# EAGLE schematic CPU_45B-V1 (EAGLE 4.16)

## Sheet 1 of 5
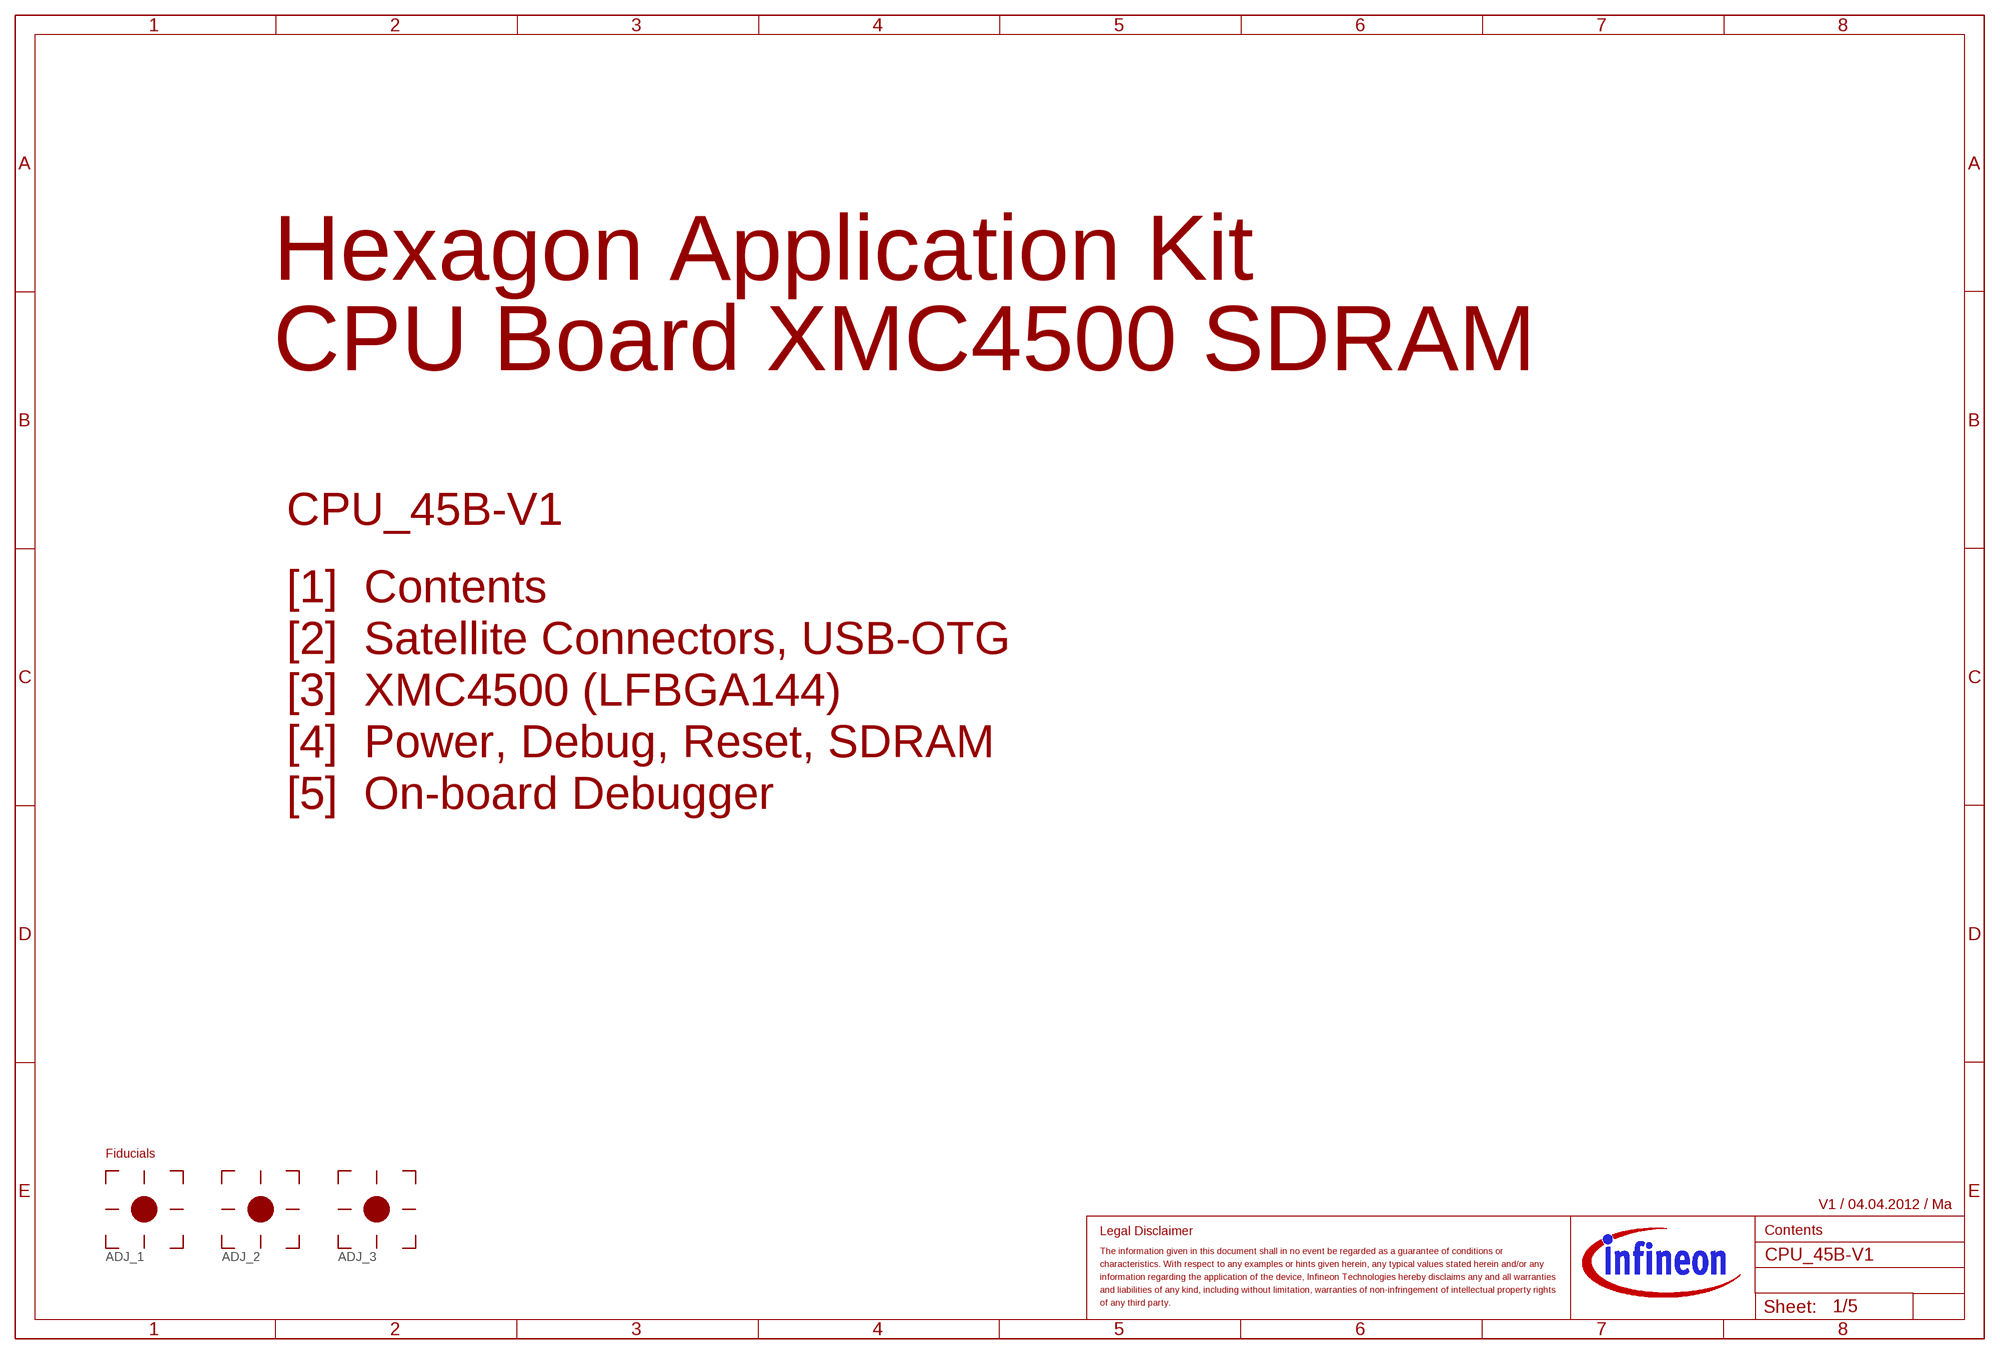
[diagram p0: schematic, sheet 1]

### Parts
ADJ_1  FIDUCIAL  [FIDUCIAL]
ADJ_2  FIDUCIAL  [FIDUCIAL]
ADJ_3  FIDUCIAL  [FIDUCIAL]

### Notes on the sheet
- Hexagon Application Kit
- CPU Board XMC4500 SDRAM
- CPU_45B-V1
- [1]  Contents
- [2]  Satellite Connectors, USB-OTG
- [3]  XMC4500 (LFBGA144)
- [4]  Power, Debug, Reset, SDRAM
- [5]  On-board Debugger
- Fiducials
- V1 / 04.04.2012 / Ma
- Contents

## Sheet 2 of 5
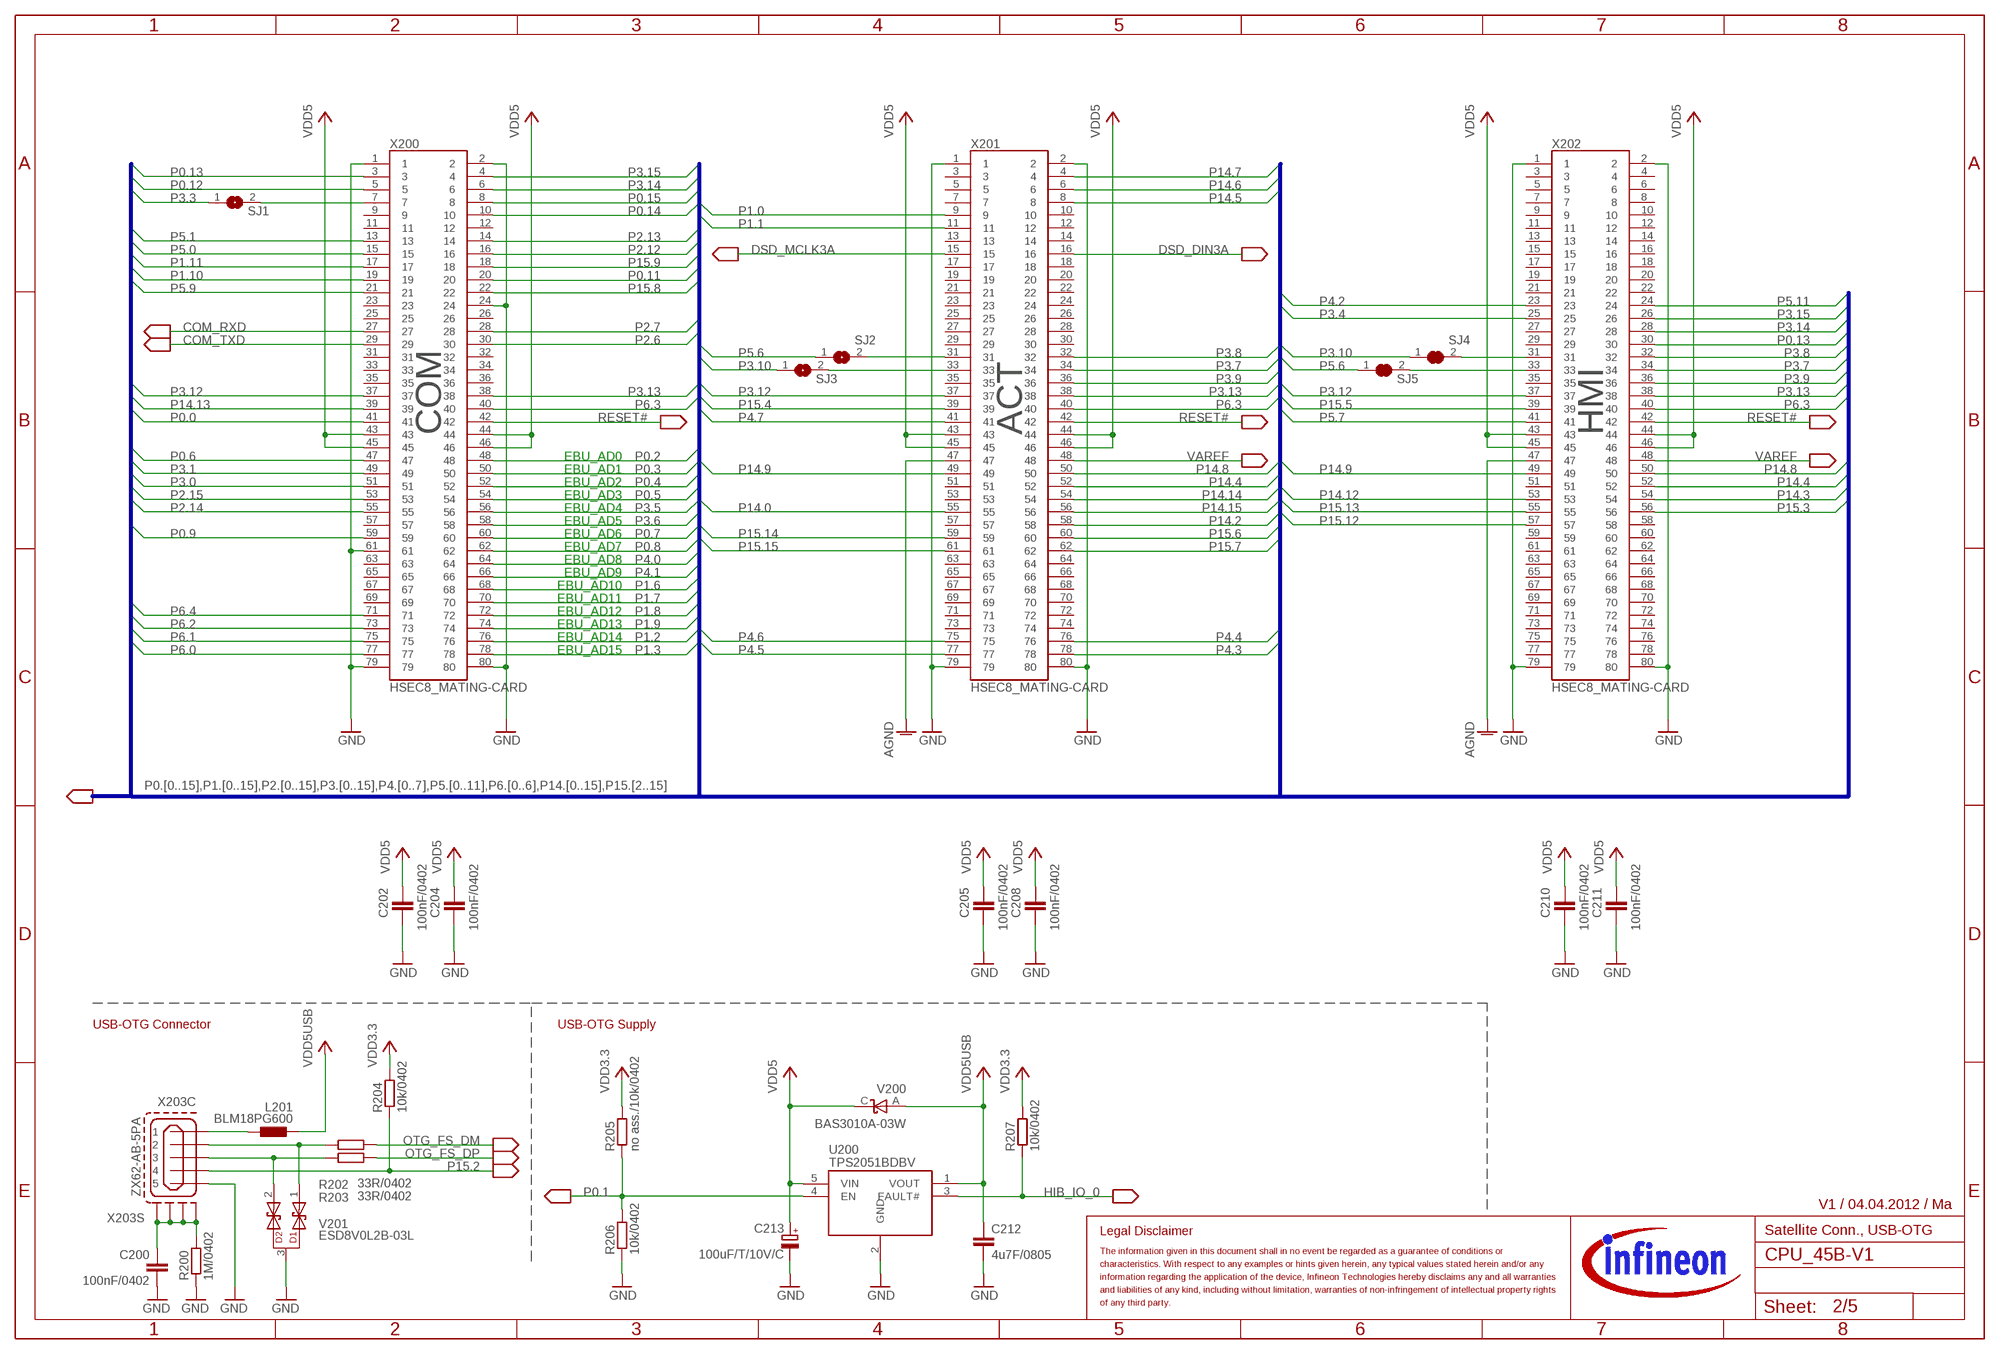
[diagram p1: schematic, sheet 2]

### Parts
C200  100nF/0402  C-EUC06030402  [C0402]
C202  100nF/0402  C-EUC06030402  [C0402]
C204  100nF/0402  C-EUC06030402  [C0402]
C205  100nF/0402  C-EUC06030402  [C0402]
C208  100nF/0402  C-EUC06030402  [C0402]
C210  100nF/0402  C-EUC06030402  [C0402]
C211  100nF/0402  C-EUC06030402  [C0402]
C212  4u7F/0805  C-EUC0805K  [C0805K]
C213  100uF/T/10V/C  CPOL-EUSMCC  [SMC_C]
L201  BLM18PG600  L_EU_L0603  [L1608]
R200  1M/0402  R-EU_R06030402  [R0402]
R202  33R/0402  R-EU_R06030402  [R0402]
R203  33R/0402  R-EU_R06030402  [R0402]
R204  10k/0402  R-EU_R06030402  [R0402]
R205  no ass./10k/0402  R-EU_R06030402  [R0402]
R206  10k/0402  R-EU_R06030402  [R0402]
R207  10k/0402  R-EU_R06030402  [R0402]
SJ1  SJ0402PASTE  [R0402]
SJ2  SJ0402PASTE  [R0402]
SJ3  SJ0402PASTE  [R0402]
SJ4  SJ0402PASTE  [R0402]
SJ5  SJ0402PASTE  [R0402]
U200  TPS2051BDBV  STMPS2151STR  [SOT23-5L]
V200  BAS3010A-03W  BAT60  [SOD323-R]
V201  ESD8V0L2B-03L  [TSLP-3-1]
X200  HSEC8_MATING-CARD  [HSEC8_MATING-CARD_80]
X201  HSEC8_MATING-CARD  [HSEC8_MATING-CARD_80]
X202  HSEC8_MATING-CARD  [HSEC8_MATING-CARD_80]
X203  ZX62-AB-5PA  ZX62-AB-5PA_MICRO-USB  [ZX62-AB-5PA_MICRO-USB]

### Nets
AGND: X201.47 X202.47 ; also sheet 3
COM_RXD: X200.27 ; also sheet 3
COM_TXD: X200.29 ; also sheet 3
DSD_DIN3A: X201.16 ; also sheet 3
DSD_MCLK3A: X201.15 ; also sheet 3
GND: C200.2 C202.2 C204.2 C205.2 C208.2 C210.2 C211.2 C212.2 C213.- R200.1 R206.1 U200.2(GND) V201.3 X200.1 X200.2 X200.24 X200.61 X200.79 X200.80 X201.1 X201.2 X201.79 X201.80 X202.1 X202.2 X202.79 X202.80 X203.5 ; also sheet 3,4,5
HIB_IO_0: R207.1 U200.3(FAULT#) ; also sheet 3
N$4: L201.1 X203.1
N$5: R203.1 V201.2 X203.3
N$6: R202.1 V201.1 X203.2
N$28: C200.1 R200.2 X203.S1(S:S1) X203.S2(S:S2) X203.S3(S:S3) X203.S4(S:S4)
N$32: SJ3.2 X201.33
N$48: SJ5.2 X202.33
N$49: SJ1.2 X200.7
N$52: SJ4.2 X202.31
N$53: SJ2.2 X201.31
OTG_FS_DM: R202.2 ; also sheet 3
OTG_FS_DP: R203.2 ; also sheet 3
P0.0: X200.41 ; also sheet 3
P0.1: R205.1 R206.2 U200.4(EN) ; also sheet 3
P0.2: X200.48 ; also sheet 3,4
P0.3: X200.50 ; also sheet 3,4
P0.4: X200.52 ; also sheet 3,4
P0.5: X200.54 ; also sheet 3,4
P0.6: X200.47 ; also sheet 3
P0.7: X200.60 ; also sheet 3,4,5
P0.8: X200.62 ; also sheet 3,4
P0.9: X200.59 ; also sheet 3
P0.11: X200.20 ; also sheet 3
P0.12: X200.5 ; also sheet 3
P0.13: X200.3 X202.30 ; also sheet 3
P0.14: X200.10 ; also sheet 3
P0.15: X200.8 ; also sheet 3
P1.0: X201.9 ; also sheet 3
P1.1: X201.11 ; also sheet 3
P1.2: X200.76 ; also sheet 3,4
P1.3: X200.78 ; also sheet 3,4
P1.6: X200.68 ; also sheet 3,4
P1.7: X200.70 ; also sheet 3,4
P1.8: X200.72 ; also sheet 3,4
P1.9: X200.74 ; also sheet 3,4
P1.10: X200.19 ; also sheet 3
P1.11: X200.17 ; also sheet 3
P2.6: X200.30 ; also sheet 3
P2.7: X200.28 ; also sheet 3
P2.12: X200.16 ; also sheet 3
P2.13: X200.14 ; also sheet 3
P2.14: X200.55 ; also sheet 3,4
P2.15: X200.53 ; also sheet 3,4
P3.0: X200.51 ; also sheet 3
P3.1: X200.49 ; also sheet 3,4
P3.3: SJ1.1 ; also sheet 3
P3.4: X202.25 ; also sheet 3
P3.5: X200.56 ; also sheet 3,4
P3.6: X200.58 ; also sheet 3,4
P3.7: X201.34 X202.34 ; also sheet 3
P3.8: X201.32 X202.32 ; also sheet 3
P3.9: X201.36 X202.36 ; also sheet 3
P3.10: SJ3.1 SJ4.1 ; also sheet 3
P3.12: X200.37 X201.37 X202.37 ; also sheet 3
P3.13: X200.38 X201.38 X202.38 ; also sheet 3
P3.14: X200.6 X202.28 ; also sheet 3
P3.15: X200.4 X202.26 ; also sheet 3
P4.0: X200.64 ; also sheet 3,4
P4.1: X200.66 ; also sheet 3,4
P4.2: X202.23 ; also sheet 3
P4.3: X201.78 ; also sheet 3
P4.4: X201.76 ; also sheet 3
P4.5: X201.77 ; also sheet 3
P4.6: X201.75 ; also sheet 3
P4.7: X201.41 ; also sheet 3
P5.0: X200.15 ; also sheet 3
P5.1: X200.13 ; also sheet 3
P5.6: SJ2.1 SJ5.1 ; also sheet 3
P5.7: X202.41 ; also sheet 3
P5.9: X200.21 ; also sheet 3
P5.11: X202.24 ; also sheet 3
P6.0: X200.77 ; also sheet 3,4
P6.1: X200.75 ; also sheet 3,4
P6.2: X200.73 ; also sheet 3,4
P6.3: X200.40 X201.40 X202.40 ; also sheet 3
P6.4: X200.71 ; also sheet 3,4
P14.0: X201.55 ; also sheet 3
P14.2: X201.58 ; also sheet 3
P14.3: X202.54 ; also sheet 3
P14.4: X201.52 X202.52 ; also sheet 3
P14.5: X201.8 ; also sheet 3
P14.6: X201.6 ; also sheet 3
P14.7: X201.4 ; also sheet 3
P14.8: X201.50 X202.50 ; also sheet 3
P14.9: X201.49 X202.49 ; also sheet 3
P14.12: X202.53 ; also sheet 3
P14.13: X200.39 ; also sheet 3
P14.14: X201.54 ; also sheet 3
P14.15: X201.56 ; also sheet 3
P15.2: R204.1 X203.4 ; also sheet 3
P15.3: X202.56 ; also sheet 3
P15.4: X201.39 ; also sheet 3
P15.5: X202.39 ; also sheet 3
P15.6: X201.60 ; also sheet 3
P15.7: X201.62 ; also sheet 3
P15.8: X200.22 ; also sheet 3
P15.9: X200.18 ; also sheet 3
P15.12: X202.57 ; also sheet 3
P15.13: X202.55 ; also sheet 3
P15.14: X201.59 ; also sheet 3
P15.15: X201.61 ; also sheet 3
RESET#: X200.42 X201.42 X202.42 ; also sheet 3,4,5
VAREF: X201.48 X202.48 ; also sheet 3
VDD3.3: R204.2 R205.2 R207.2 ; also sheet 3,4,5
VDD5: C202.1 C204.1 C205.1 C208.1 C210.1 C211.1 C213.+ U200.5(VIN) V200.C X200.43 X200.44 X200.45 X200.46 X201.43 X201.44 X201.45 X201.46 X202.43 X202.44 X202.45 X202.46 ; also sheet 4,5
VDD5USB: C212.1 L201.2 U200.1(VOUT) V200.A ; also sheet 3,4
Unconnected: X200.9 X200.11 X200.12 X200.23 X200.25 X200.26 X200.31 X200.32 X200.33 X200.34 X200.35 X200.36 X200.57 X200.63 X200.65 X200.67 X200.69 X201.3 X201.5 X201.7 X201.10 X201.12 X201.13 X201.14 X201.17 X201.18 X201.19 X201.20 X201.21 X201.22 X201.23 X201.24 X201.25 X201.26 X201.27 X201.28 X201.29 X201.30 X201.35 X201.51 X201.53 X201.57 X201.63 X201.64 X201.65 X201.66 X201.67 X201.68 X201.69 X201.70 X201.71 X201.72 X201.73 X201.74 X202.3 X202.4 X202.5 X202.6 X202.7 X202.8 X202.9 X202.10 X202.11 X202.12 X202.13 X202.14 X202.15 X202.16 X202.17 X202.18 X202.19 X202.20 X202.21 X202.22 X202.27 X202.29 X202.35 X202.51 X202.58 X202.59 X202.60 X202.61 X202.62 X202.63 X202.64 X202.65 X202.66 X202.67 X202.68 X202.69 X202.70 X202.71 X202.72 X202.73 X202.74 X202.75 X202.76 X202.77 X202.78

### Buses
P0.[0..15],P1.[0..15],P2.[0..15],P3.[0..15],P4.[0..7],P5.[0..11],P6.[0..6],P14.[0..15],P15.[2..15]

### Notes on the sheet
- COM | ACT | HMI
- EBU_AD0
- EBU_AD1
- EBU_AD2
- EBU_AD3
- EBU_AD4
- EBU_AD5
- EBU_AD6
- EBU_AD7
- EBU_AD8
- EBU_AD9
- EBU_AD10
- EBU_AD11
- EBU_AD12
- EBU_AD13
- EBU_AD14
- EBU_AD15
- USB-OTG Connector | USB-OTG Supply
- V1 / 04.04.2012 / Ma
- Satellite Conn., USB-OTG

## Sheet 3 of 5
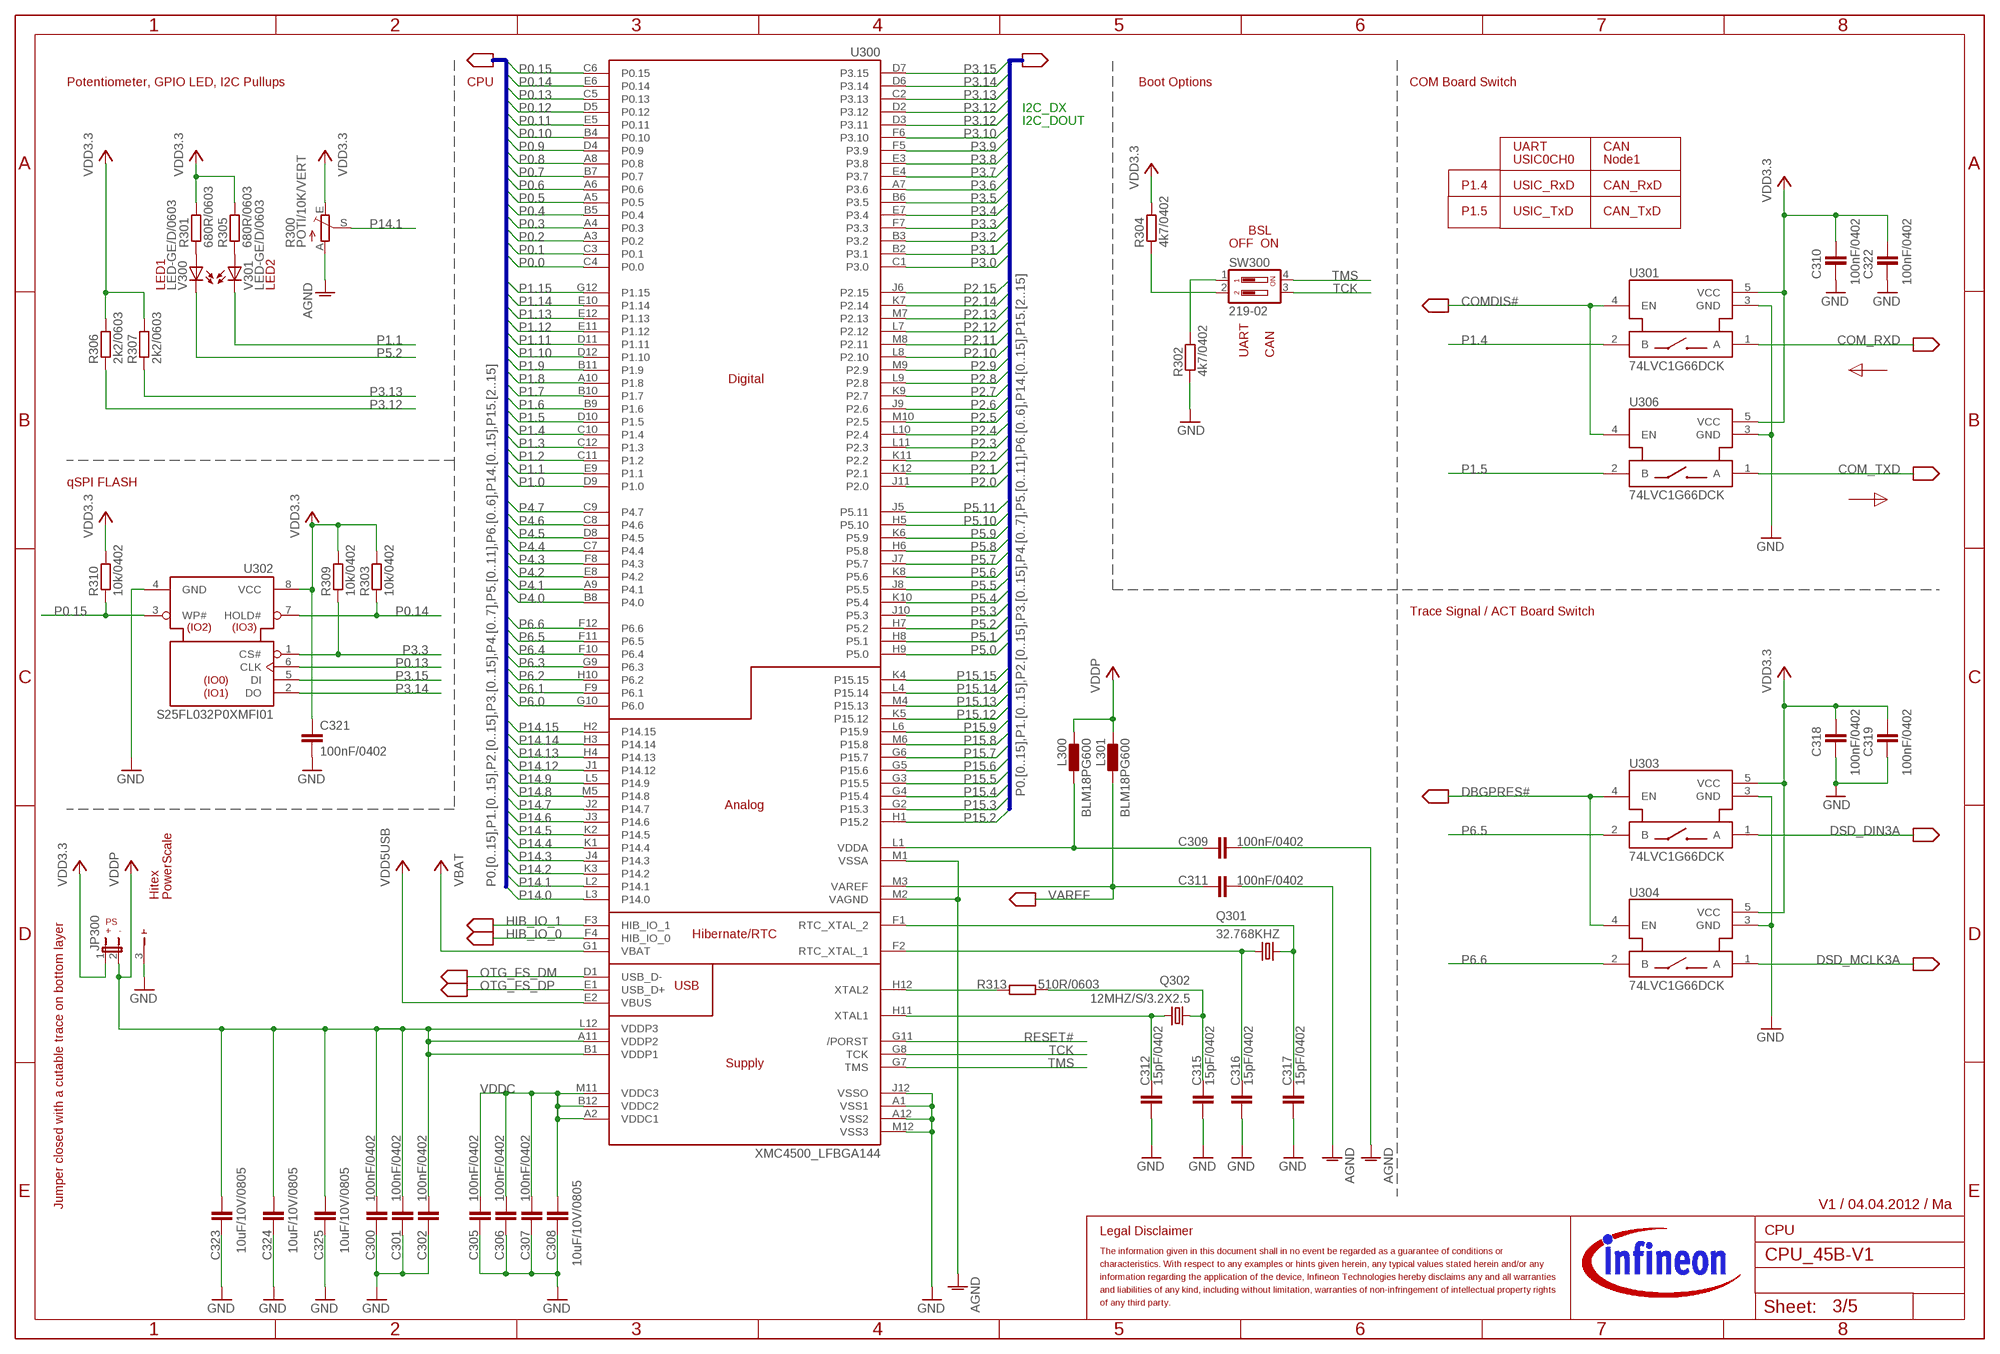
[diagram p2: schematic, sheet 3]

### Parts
C300  100nF/0402  C-EUC06030402  [C0402]
C301  100nF/0402  C-EUC06030402  [C0402]
C302  100nF/0402  C-EUC06030402  [C0402]
C305  100nF/0402  C-EUC06030402  [C0402]
C306  100nF/0402  C-EUC06030402  [C0402]
C307  100nF/0402  C-EUC06030402  [C0402]
C308  10uF/10V/0805  C-EUC0805K  [C0805K]
C309  100nF/0402  C-EUC06030402  [C0402]
C310  100nF/0402  C-EUC06030402  [C0402]
C311  100nF/0402  C-EUC06030402  [C0402]
C312  15pF/0402  C-EUC06030402  [C0402]
C315  15pF/0402  C-EUC06030402  [C0402]
C316  15pF/0402  C-EUC06030402  [C0402]
C317  15pF/0402  C-EUC06030402  [C0402]
C318  100nF/0402  C-EUC06030402  [C0402]
C319  100nF/0402  C-EUC06030402  [C0402]
C321  100nF/0402  C-EUC06030402  [C0402]
C322  100nF/0402  C-EUC06030402  [C0402]
C323  10uF/10V/0805  C-EUC0805K  [C0805K]
C324  10uF/10V/0805  C-EUC0805K  [C0805K]
C325  10uF/10V/0805  C-EUC0805K  [C0805K]
JP300  POWERSCALEMIR_SW  [PS3_MIRROR_SW]
L300  BLM18PG600  L_EU_L0603  [L1608]
L301  BLM18PG600  L_EU_L0603  [L1608]
Q301  32.768KHZ  FC135-32.768KHZ  [FC-135]
Q302  12MHZ/S/3.2X2.5  NX3225_22PAD  [32X25_2PAD]
R300  POTI/10K/VERT  [POTI]
R301  680R/0603  R-EU_R0603  [R0603]
R302  4k7/0402  R-EU_R06030402  [R0402]
R303  10k/0402  R-EU_R06030402  [R0402]
R304  4k7/0402  R-EU_R06030402  [R0402]
R305  680R/0603  R-EU_R0603  [R0603]
R306  2k2/0603  R-EU_R0603  [R0603]
R307  2k2/0603  R-EU_R0603  [R0603]
R309  10k/0402  R-EU_R06030402  [R0402]
R310  10k/0402  R-EU_R06030402  [R0402]
R313  510R/0603  R-EU_R0603  [R0603]
SW300  219-02  [CTS-219-02]
U300  XMC4500_LFBGA144  [P/PG-LFBGA-144-9]
U301  74LVC1G66DCK  74LVC1G66+PWRDCK  [SC70-5L]
U302  S25FL032P0XMFI01  W25Q80BVSSIG  [SO08W]
U303  74LVC1G66DCK  74LVC1G66+PWRDCK  [SC70-5L]
U304  74LVC1G66DCK  74LVC1G66+PWRDCK  [SC70-5L]
U306  74LVC1G66DCK  74LVC1G66+PWRDCK  [SC70-5L]
V300  LED-GE/D/0603  LEDCHIPLED_0603  [CHIPLED_0603]
V301  LED-GE/D/0603  LEDCHIPLED_0603  [CHIPLED_0603]

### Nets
AGND: C309.2 C311.2 R300.A U300.M1(VSSA) U300.M2(VAGND) ; also sheet 2
COM_RXD: U301.1(A) ; also sheet 2
COM_TXD: U306.1(A) ; also sheet 2
COMDIS#: U301.4(EN) U306.4(EN) ; also sheet 4,5
DBGPRES#: U303.4(EN) U304.4(EN) ; also sheet 4,5
DSD_DIN3A: U303.1(A) ; also sheet 2
DSD_MCLK3A: U304.1(A) ; also sheet 2
GND: C300.2 C301.2 C302.2 C305.2 C306.2 C307.2 C308.2 C310.2 C312.2 C315.2 C316.2 C317.2 C318.2 C319.2 C321.2 C322.2 C323.2 C324.2 C325.2 JP300.3(G) R302.1 U300.A1(VSS1) U300.A12(VSS2) U300.J12(VSSO) U300.M12(VSS3) U301.3(GND) U302.4(GND) U303.3(GND) U304.3(GND) U306.3(GND) ; also sheet 2,4,5
HIB_IO_0: U300.F4(HIB_IO_0) ; also sheet 2
HIB_IO_1: U300.F3(HIB_IO_1) ; also sheet 4
N$1: R304.1 SW300.2
N$2: R302.2 SW300.1
N$3: C309.1 L300.1 U300.L1(VDDA)
N$13: C312.1 Q302.2 U300.H11(XTAL1)
N$33: R305.1 V301.A
N$38: C316.1 Q301.P$1 U300.F2(RTC_XTAL_1)
N$39: R301.1 V300.A
N$40: C315.1 Q302.1 R313.2
N$42: C317.1 Q301.P$2 U300.F1(RTC_XTAL_2)
N$43: R313.1 U300.H12(XTAL2)
OTG_FS_DM: U300.D1(USB_D-) ; also sheet 2
OTG_FS_DP: U300.E1(USB_D+) ; also sheet 2
P0.0: U300.C4(P0.0) ; also sheet 2
P0.1: U300.C3(P0.1) ; also sheet 2
P0.2: U300.A3(P0.2) ; also sheet 2,4
P0.3: U300.A4(P0.3) ; also sheet 2,4
P0.4: U300.B5(P0.4) ; also sheet 2,4
P0.5: U300.A5(P0.5) ; also sheet 2,4
P0.6: U300.A6(P0.6) ; also sheet 2
P0.7: U300.B7(P0.7) ; also sheet 2,4,5
P0.8: U300.A8(P0.8) ; also sheet 2,4
P0.9: U300.D4(P0.9) ; also sheet 2
P0.10: U300.B4(P0.10) ; also sheet 4
P0.11: U300.E5(P0.11) ; also sheet 2
P0.12: U300.D5(P0.12) ; also sheet 2
P0.13: U300.C5(P0.13) U302.6(CLK) ; also sheet 2
P0.14: R303.1 U300.E6(P0.14) U302.7(HOLD#) ; also sheet 2
P0.15: R310.1 U300.C6(P0.15) U302.3(WP#) ; also sheet 2
P1.0: U300.D9(P1.0) ; also sheet 2
P1.1: U300.E9(P1.1) V301.C ; also sheet 2
P1.2: U300.C11(P1.2) ; also sheet 2,4
P1.3: U300.C12(P1.3) ; also sheet 2,4
P1.4: U300.C10(P1.4) U301.2(B) ; also sheet 4,5
P1.5: U300.D10(P1.5) U306.2(B) ; also sheet 4,5
P1.6: U300.B9(P1.6) ; also sheet 2,4
P1.7: U300.B10(P1.7) ; also sheet 2,4
P1.8: U300.A10(P1.8) ; also sheet 2,4
P1.9: U300.B11(P1.9) ; also sheet 2,4
P1.10: U300.D12(P1.10) ; also sheet 2
P1.11: U300.D11(P1.11) ; also sheet 2
P1.12: U300.E11(P1.12) ; also sheet 4
P1.13: U300.E12(P1.13) ; also sheet 4
P1.14: U300.E10(P1.14) ; also sheet 4
P1.15: U300.G12(P1.15) ; also sheet 4
P2.0: U300.J11(P2.0) ; also sheet 4
P2.1: U300.K12(P2.1) ; also sheet 4,5
P2.2: U300.K11(P2.2) ; also sheet 4
P2.3: U300.L11(P2.3) ; also sheet 4
P2.4: U300.L10(P2.4) ; also sheet 4
P2.5: U300.M10(P2.5) ; also sheet 4
P2.6: U300.J9(P2.6) ; also sheet 2
P2.7: U300.K9(P2.7) ; also sheet 2
P2.8: U300.L9(P2.8) ; also sheet 4
P2.9: U300.M9(P2.9) ; also sheet 4
P2.10: U300.L8(P2.10) ; also sheet 4
P2.11: U300.M8(P2.11) ; also sheet 4
P2.12: U300.L7(P2.12) ; also sheet 2
P2.13: U300.M7(P2.13) ; also sheet 2
P2.14: U300.K7(P2.14) ; also sheet 2,4
P2.15: U300.J6(P2.15) ; also sheet 2,4
P3.0: U300.C1(P3.0) ; also sheet 2
P3.1: U300.B2(P3.1) ; also sheet 2,4
P3.2: U300.B3(P3.2) ; also sheet 4
P3.3: R309.1 U300.F7(P3.3) U302.1(CS#) ; also sheet 2
P3.4: U300.E7(P3.4) ; also sheet 2
P3.5: U300.B6(P3.5) ; also sheet 2,4
P3.6: U300.A7(P3.6) ; also sheet 2,4
P3.7: U300.E4(P3.7) ; also sheet 2
P3.8: U300.E3(P3.8) ; also sheet 2
P3.9: U300.F5(P3.9) ; also sheet 2
P3.10: U300.F6(P3.10) ; also sheet 2
P3.12: R306.1 U300.D2(P3.12) U300.D3(P3.11) ; also sheet 2
P3.13: R307.1 U300.C2(P3.13) ; also sheet 2
P3.14: U300.D6(P3.14) U302.2(DO) ; also sheet 2
P3.15: U300.D7(P3.15) U302.5(DI) ; also sheet 2
P4.0: U300.B8(P4.0) ; also sheet 2,4
P4.1: U300.A9(P4.1) ; also sheet 2,4
P4.2: U300.E8(P4.2) ; also sheet 2
P4.3: U300.F8(P4.3) ; also sheet 2
P4.4: U300.C7(P4.4) ; also sheet 2
P4.5: U300.D8(P4.5) ; also sheet 2
P4.6: U300.C8(P4.6) ; also sheet 2
P4.7: U300.C9(P4.7) ; also sheet 2
P5.0: U300.H9(P5.0) ; also sheet 2
P5.1: U300.H8(P5.1) ; also sheet 2
P5.2: U300.H7(P5.2) V300.C
P5.3: U300.J10(P5.3) ; also sheet 4
P5.4: U300.K10(P5.4) ; also sheet 4
P5.5: U300.J8(P5.5) ; also sheet 4
P5.6: U300.K8(P5.6) ; also sheet 2
P5.7: U300.J7(P5.7) ; also sheet 2
P5.8: U300.H6(P5.8) ; also sheet 4
P5.9: U300.K6(P5.9) ; also sheet 2
P5.10: U300.H5(P5.10) ; also sheet 4
P5.11: U300.J5(P5.11) ; also sheet 2
P6.0: U300.G10(P6.0) ; also sheet 2,4
P6.1: U300.F9(P6.1) ; also sheet 2,4
P6.2: U300.H10(P6.2) ; also sheet 2,4
P6.3: U300.G9(P6.3) ; also sheet 2
P6.4: U300.F10(P6.4) ; also sheet 2,4
P6.5: U300.F11(P6.5) U303.2(B) ; also sheet 4
P6.6: U300.F12(P6.6) U304.2(B) ; also sheet 4
P14.0: U300.L3(P14.0) ; also sheet 2
P14.1: R300.S U300.L2(P14.1)
P14.2: U300.K3(P14.2) ; also sheet 2
P14.3: U300.J4(P14.3) ; also sheet 2
P14.4: U300.K1(P14.4) ; also sheet 2
P14.5: U300.K2(P14.5) ; also sheet 2
P14.6: U300.J3(P14.6) ; also sheet 2
P14.7: U300.J2(P14.7) ; also sheet 2
P14.8: U300.M5(P14.8) ; also sheet 2
P14.9: U300.L5(P14.9) ; also sheet 2
P14.12: U300.J1(P14.12) ; also sheet 2
P14.13: U300.H4(P14.13) ; also sheet 2
P14.14: U300.H3(P14.14) ; also sheet 2
P14.15: U300.H2(P14.15) ; also sheet 2
P15.2: U300.H1(P15.2) ; also sheet 2
P15.3: U300.G2(P15.3) ; also sheet 2
P15.4: U300.G4(P15.4) ; also sheet 2
P15.5: U300.G3(P15.5) ; also sheet 2
P15.6: U300.G5(P15.6) ; also sheet 2
P15.7: U300.G6(P15.7) ; also sheet 2
P15.8: U300.M6(P15.8) ; also sheet 2
P15.9: U300.L6(P15.9) ; also sheet 2
P15.12: U300.K5(P15.12) ; also sheet 2
P15.13: U300.M4(P15.13) ; also sheet 2
P15.14: U300.L4(P15.14) ; also sheet 2
P15.15: U300.K4(P15.15) ; also sheet 2
RESET#: U300.G11(/PORST) ; also sheet 2,4,5
TCK: SW300.3 U300.G8(TCK) ; also sheet 4,5
TMS: SW300.4 U300.G7(TMS) ; also sheet 4,5
VAREF: C311.1 L301.1 U300.M3(VAREF) ; also sheet 2
VBAT: U300.G1(VBAT) ; also sheet 4
VDD3.3: C310.1 C318.1 C319.1 C321.1 C322.1 JP300.1(P) R300.E R301.2 R303.2 R304.2 R305.2 R306.2 R307.2 R309.2 R310.2 U301.5(VCC) U302.8(VCC) U303.5(VCC) U304.5(VCC) U306.5(VCC) ; also sheet 2,4,5
VDD5USB: U300.E2(VBUS) ; also sheet 2,4
VDDC: C305.1 C306.1 C307.1 C308.1 U300.A2(VDDC1) U300.B12(VDDC2) U300.M11(VDDC3)
VDDP: C300.1 C301.1 C302.1 C323.1 C324.1 C325.1 JP300.2(M) L300.2 L301.2 U300.A11(VDDP2) U300.B1(VDDP1) U300.L12(VDDP3)

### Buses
P0.[0..15],P1.[0..15],P2.[0..15],P3.[0..15],P4.[0..7],P5.[0..11],P6.[0..6],P14.[0..15],P15.[2..15]

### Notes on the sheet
- Potentiometer, GPIO LED, I2C Pullups | CPU | Boot Options | COM Board Switch
- I2C_DX
- I2C_DOUT
- UART | CAN
- USIC0CH0 | Node1
- P1.4 | USIC_RxD | CAN_RxD
- P1.5 | USIC_TxD | CAN_TxD
- BSL
- OFF  ON
- LED1 | LED2
- UART | CAN
- qSPI FLASH
- Trace Signal / ACT Board Switch
- Hitex | PowerScale
- Jumper closed with a cutable trace on bottom layer | V1 / 04.04.2012 / Ma
- CPU

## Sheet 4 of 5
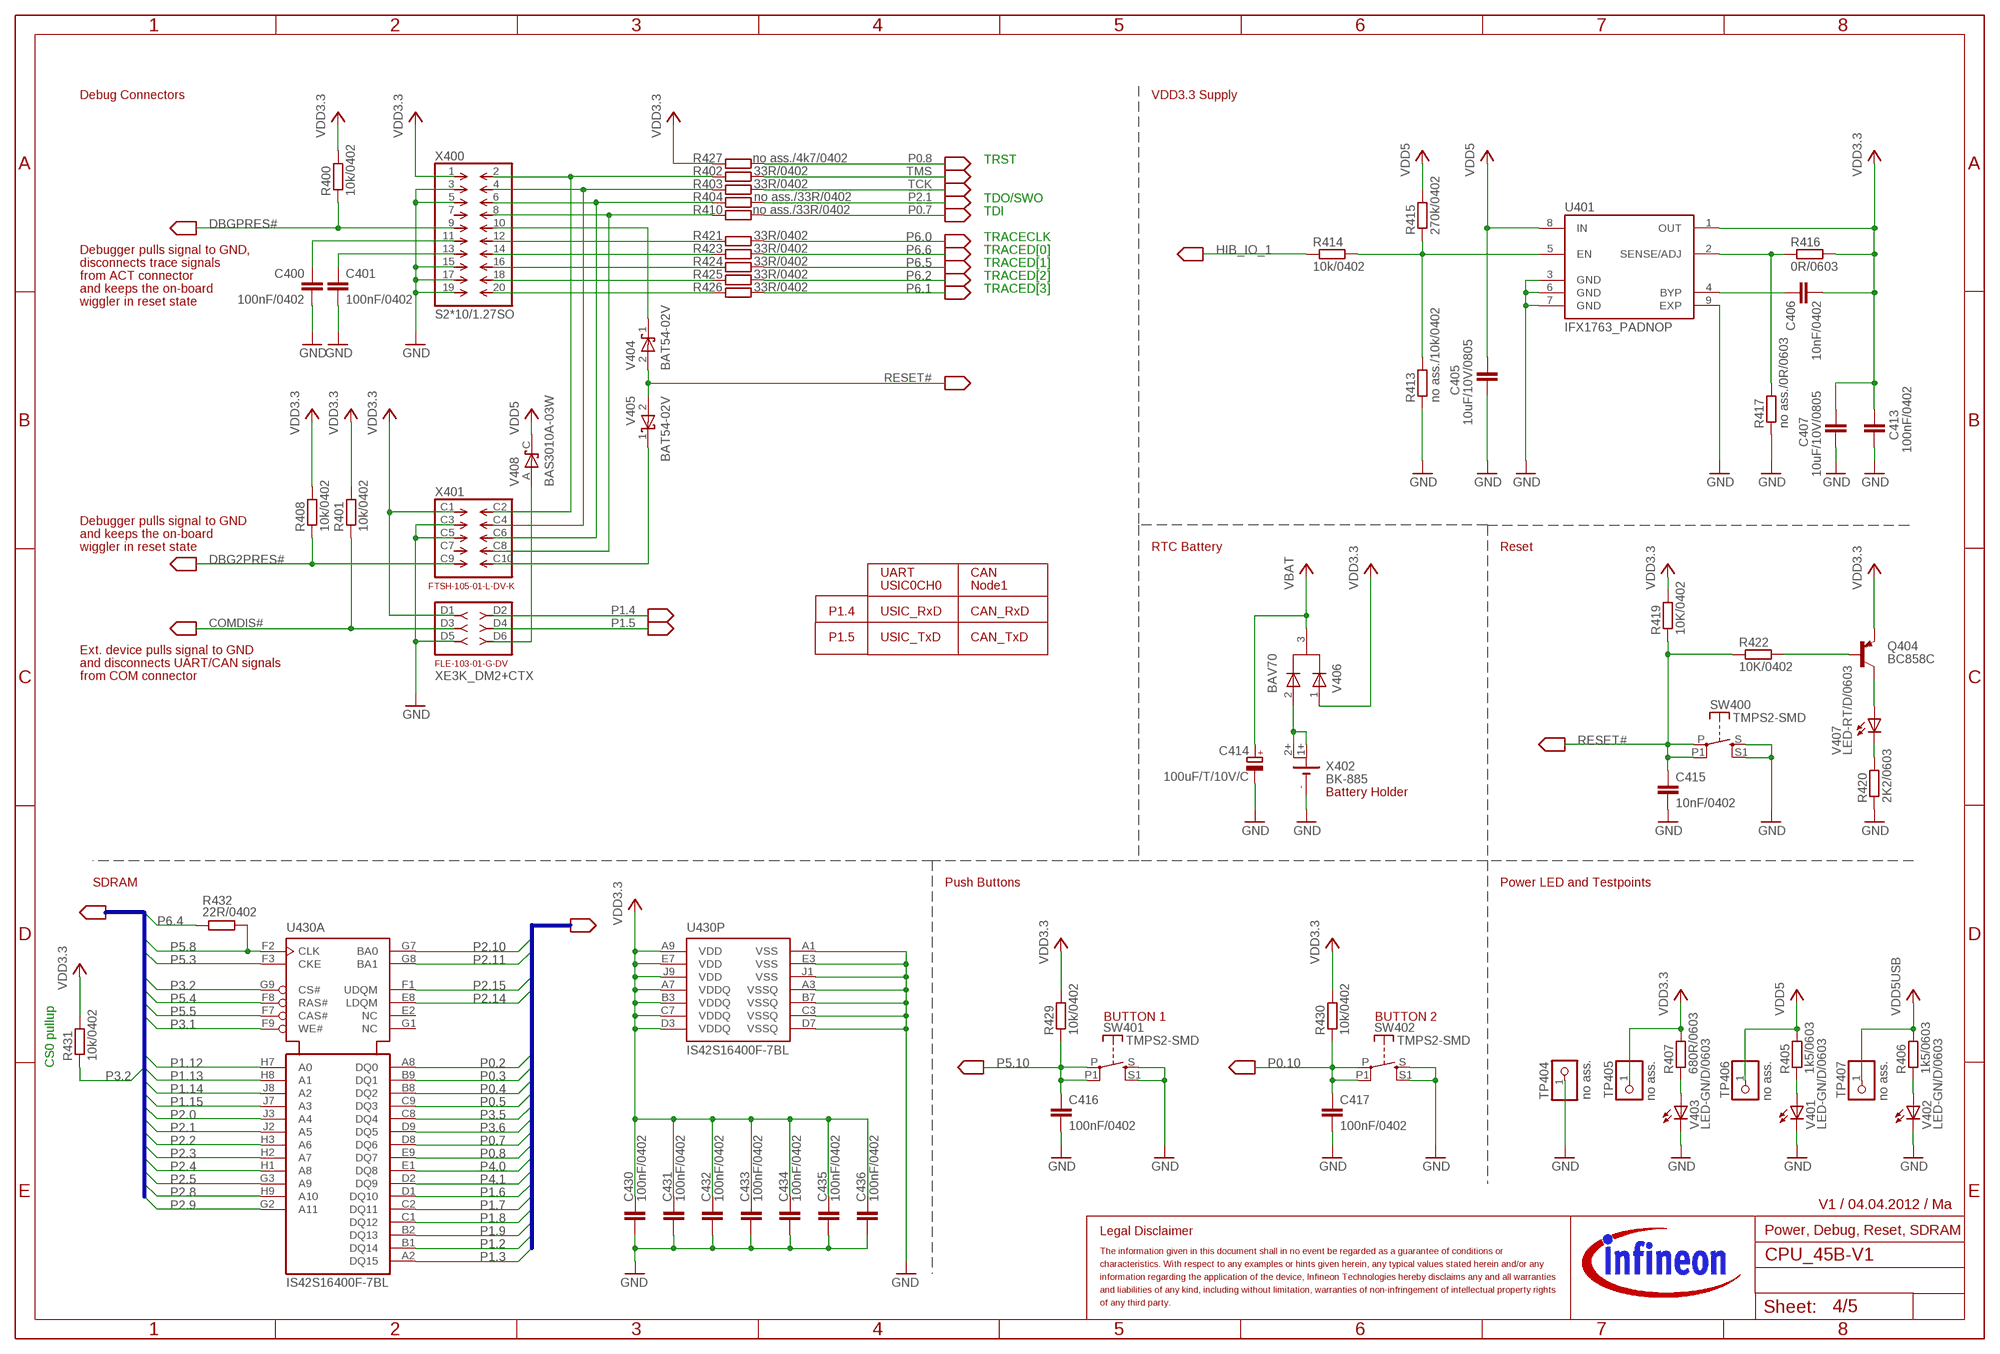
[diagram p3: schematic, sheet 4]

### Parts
C400  100nF/0402  C-EUC0402  [C0402]
C401  100nF/0402  C-EUC0402  [C0402]
C405  10uF/10V/0805  C-EUC0805K  [C0805K]
C406  10nF/0402  C-EUC06030402  [C0402]
C407  10uF/10V/0805  C-EUC0805K  [C0805K]
C413  100nF/0402  C-EUC06030402  [C0402]
C414  100uF/T/10V/C  CPOL-EUSMCC  [SMC_C]
C415  10nF/0402  C-EUC06030402  [C0402]
C416  100nF/0402  C-EUC06030402  [C0402]
C417  100nF/0402  C-EUC06030402  [C0402]
C430  100nF/0402  C-EUC06030402  [C0402]
C431  100nF/0402  C-EUC06030402  [C0402]
C432  100nF/0402  C-EUC06030402  [C0402]
C433  100nF/0402  C-EUC06030402  [C0402]
C434  100nF/0402  C-EUC06030402  [C0402]
C435  100nF/0402  C-EUC06030402  [C0402]
C436  100nF/0402  C-EUC06030402  [C0402]
Q404  BC858C  [TO236]
R400  10k/0402  R-EU_R06030402  [R0402]
R401  10k/0402  R-EU_R06030402  [R0402]
R402  33R/0402  R-EU_R0402  [R0402]
R403  33R/0402  R-EU_R0402  [R0402]
R404  no ass./33R/0402  R-EU_R0402  [R0402]
R405  1k5/0603  R-EU_R0603  [R0603]
R406  1k5/0603  R-EU_R0603  [R0603]
R407  680R/0603  R-EU_R0603  [R0603]
R408  10k/0402  R-EU_R06030402  [R0402]
R410  no ass./33R/0402  R-EU_R0402  [R0402]
R413  no ass./10k/0402  R-EU_R06030402  [R0402]
R414  10k/0402  R-EU_R06030402  [R0402]
R415  270k/0402  R-EU_R06030402  [R0402]
R416  0R/0603  R-EU_R0603  [R0603]
R417  no ass./0R/0603  R-EU_R0603  [R0603]
R419  10K/0402  R-EU_R06030402  [R0402]
R420  2K2/0603  R-EU_R0603  [R0603]
R421  33R/0402  R-EU_R0402  [R0402]
R422  10K/0402  R-EU_R06030402  [R0402]
R423  33R/0402  R-EU_R0402  [R0402]
R424  33R/0402  R-EU_R0402  [R0402]
R425  33R/0402  R-EU_R0402  [R0402]
R426  33R/0402  R-EU_R0402  [R0402]
R427  no ass./4k7/0402  R-EU_R0402  [R0402]
R429  10k/0402  R-EU_R06030402  [R0402]
R430  10k/0402  R-EU_R06030402  [R0402]
R431  10k/0402  R-EU_R06030402  [R0402]
R432  22R/0402  R-EU_R06030402  [R0402]
SW400  TMPS2-SMD  FSM2JSMA  [FSM2JSMA]
SW401  TMPS2-SMD  FSM2JSMA  [FSM2JSMA]
SW402  TMPS2-SMD  FSM2JSMA  [FSM2JSMA]
TP404  no ass.  PINHD-1X1  [1X01]
TP405  no ass.  PINHD-1X1  [1X01]
TP406  no ass.  PINHD-1X1  [1X01]
TP407  no ass.  PINHD-1X1  [1X01]
U401  IFX1763_PADNOP  [PG-DSO-8-27_NO-PASTE]
U430  IS42S16400F-7BL  MT48LC4M16A2B4-7E  [VFBGA54-6X9_8MMX8MM]
V401  LED-GN/D/0603  LEDCHIPLED_0603  [CHIPLED_0603]
V402  LED-GN/D/0603  LEDCHIPLED_0603  [CHIPLED_0603]
V403  LED-GN/D/0603  LEDCHIPLED_0603  [CHIPLED_0603]
V404  BAT54-02V  [SC79]
V405  BAT54-02V  [SC79]
V406  BAV70  [SOT23-3]
V407  LED-RT/D/0603  LEDCHIPLED_0603  [CHIPLED_0603]
V408  BAS3010A-03W  BAT60  [SOD323-R]
X400  S2*10/1.27SO  FTSH-110-01-L-DV-K-P  [FTSH-110-01-L-DV-K-P]
X401  XE3K_DM2+CTX  [XE3K_DM2+CTX]
X402  BK-885  [BK-885]

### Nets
COMDIS#: R401.1 X401.D3 ; also sheet 3,5
DBG2PRES#: R408.1 X401.C9 ; also sheet 5
DBGPRES#: R400.1 X400.9 ; also sheet 3,5
GND: C400.2 C401.2 C405.2 C407.2 C413.2 C414.- C415.2 C416.2 C417.2 C430.2 C431.2 C432.2 C433.2 C434.2 C435.2 C436.2 R413.1 R417.1 R420.1 SW400.S SW400.S1(S) SW401.S SW401.S1(S) SW402.S SW402.S1(S) TP404.1 U401.3(GND) U401.6(GND) U401.7(GND) U401.9(EXP) U430.A1(P:VSS) U430.A3(P:VSSQ) U430.B7(P:VSSQ) U430.C3(P:VSSQ) U430.D7(P:VSSQ) U430.E3(P:VSS) U430.J1(P:VSS) V401.C V402.C V403.C X400.3 X400.5 X400.15 X400.17 X400.19 X401.C3 X401.C5 X401.D5 X402.- ; also sheet 2,3,5
HIB_IO_1: R414.1 ; also sheet 3
N$7: R421.1 X400.12
N$8: R423.1 X400.14
N$9: R413.2 R414.2 R415.1 U401.5(EN)
N$10: V406.2(A2) X402.1+(+) X402.2+(+)
N$11: R424.1 X400.16
N$12: R425.1 X400.18
N$14: C400.1 X400.11
N$15: V405.1(C) X401.C10
N$16: V404.1(C) X400.10
N$17: R410.1 X400.8 X401.C8
N$18: R404.1 X400.6 X401.C6
N$19: R403.1 X400.4 X401.C4
N$20: R402.1 X400.2 X401.C2
N$21: C401.1 X400.13
N$22: R405.1 V401.A
N$23: R426.1 X400.20
N$24: R406.1 V402.A
N$25: R407.1 V403.A
N$26: V408.A X401.D6
N$27: R420.2 V407.C
N$31: C406.1 U401.4(BYP)
N$35: Q404.3(C) V407.A
N$36: Q404.1(B) R422.2
N$68: R416.1 R417.2 U401.2(SENSE/ADJ)
P0.2: U430.A8(A:DQ0) ; also sheet 2,3
P0.3: U430.B9(A:DQ1) ; also sheet 2,3
P0.4: U430.B8(A:DQ2) ; also sheet 2,3
P0.5: U430.C9(A:DQ3) ; also sheet 2,3
P0.7: R410.2 U430.D8(A:DQ6) ; also sheet 2,3,5
P0.8: R427.2 U430.E9(A:DQ7) ; also sheet 2,3
P0.10: C417.1 R430.1 SW402.P SW402.P1(P) ; also sheet 3
P1.2: U430.B1(A:DQ14) ; also sheet 2,3
P1.3: U430.A2(A:DQ15) ; also sheet 2,3
P1.4: X401.D2 ; also sheet 3,5
P1.5: X401.D4 ; also sheet 3,5
P1.6: U430.D1(A:DQ10) ; also sheet 2,3
P1.7: U430.C2(A:DQ11) ; also sheet 2,3
P1.8: U430.C1(A:DQ12) ; also sheet 2,3
P1.9: U430.B2(A:DQ13) ; also sheet 2,3
P1.12: U430.H7(A:A0) ; also sheet 3
P1.13: U430.H8(A:A1) ; also sheet 3
P1.14: U430.J8(A:A2) ; also sheet 3
P1.15: U430.J7(A:A3) ; also sheet 3
P2.0: U430.J3(A:A4) ; also sheet 3
P2.1: R404.2 U430.J2(A:A5) ; also sheet 3,5
P2.2: U430.H3(A:A6) ; also sheet 3
P2.3: U430.H2(A:A7) ; also sheet 3
P2.4: U430.H1(A:A8) ; also sheet 3
P2.5: U430.G3(A:A9) ; also sheet 3
P2.8: U430.H9(A:A10) ; also sheet 3
P2.9: U430.G2(A:A11) ; also sheet 3
P2.10: U430.G7(A:BA0) ; also sheet 3
P2.11: U430.G8(A:BA1) ; also sheet 3
P2.14: U430.E8(A:LDQM) ; also sheet 2,3
P2.15: U430.F1(A:UDQM) ; also sheet 2,3
P3.1: U430.F9(A:WE#) ; also sheet 2,3
P3.2: R431.1 U430.G9(A:CS#) ; also sheet 3
P3.5: U430.C8(A:DQ4) ; also sheet 2,3
P3.6: U430.D9(A:DQ5) ; also sheet 2,3
P4.0: U430.E1(A:DQ8) ; also sheet 2,3
P4.1: U430.D2(A:DQ9) ; also sheet 2,3
P5.3: U430.F3(A:CKE) ; also sheet 3
P5.4: U430.F8(A:RAS#) ; also sheet 3
P5.5: U430.F7(A:CAS#) ; also sheet 3
P5.8: R432.2 U430.F2(A:CLK) ; also sheet 3
P5.10: C416.1 R429.1 SW401.P SW401.P1(P) ; also sheet 3
P6.0: R421.2 ; also sheet 2,3
P6.1: R426.2 ; also sheet 2,3
P6.2: R425.2 ; also sheet 2,3
P6.4: R432.1 ; also sheet 2,3
P6.5: R424.2 ; also sheet 3
P6.6: R423.2 ; also sheet 3
RESET#: C415.1 R419.1 R422.1 SW400.P SW400.P1(P) V404.2(A) V405.2(A) ; also sheet 2,3,5
TCK: R403.2 ; also sheet 3,5
TMS: R402.2 ; also sheet 3,5
VBAT: C414.+ V406.3(C) ; also sheet 3
VDD3.3: C406.2 C407.1 C413.1 C430.1 C431.1 C432.1 C433.1 C434.1 C435.1 C436.1 Q404.2(E) R400.2 R401.2 R407.2 R408.2 R416.2 R419.2 R427.1 R429.2 R430.2 R431.2 TP405.1 U401.1(OUT) U430.A7(P:VDDQ) U430.A9(P:VDD) U430.B3(P:VDDQ) U430.C7(P:VDDQ) U430.D3(P:VDDQ) U430.E7(P:VDD) U430.J9(P:VDD) V406.1(A1) X400.1 X401.C1 X401.D1 ; also sheet 2,3,5
VDD5: C405.1 R405.2 R415.2 TP406.1 U401.8(IN) V408.C ; also sheet 2,5
VDD5USB: R406.2 TP407.1 ; also sheet 2,3
Unconnected: U430.E2(A:NC) U430.G1(A:NC) X400.7 X401.C7

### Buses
P0.[0..15],P1.[0..15],P2.[0..15],P3.[0..15],P4.[0..7],P5.[0..11],P6.[0..6],P14.[0..15],P15.[2..15]

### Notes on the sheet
- Debug Connectors | VDD3.3 Supply
- TRST
- TDO/SWO
- TDI
- TRACECLK
- Debugger pulls signal to GND, | TRACED[0]
- disconnects trace signals | TRACED[1]
- from ACT connector | TRACED[2]
- and keeps the on-board | TRACED[3]
- wiggler in reset state
- Debugger pulls signal to GND
- and keeps the on-board
- wiggler in reset state | RTC Battery | Reset
- UART | CAN
- USIC0CH0 | Node1
- P1.4 | USIC_RxD | CAN_RxD
- P1.5 | USIC_TxD | CAN_TxD
- Ext. device pulls signal to GND
- and disconnects UART/CAN signals
- from COM connector
- Battery Holder
- SDRAM | Push Buttons | Power LED and Testpoints
- BUTTON 1 | BUTTON 2
- CS0 pullup
- V1 / 04.04.2012 / Ma
- Power, Debug, Reset, SDRAM

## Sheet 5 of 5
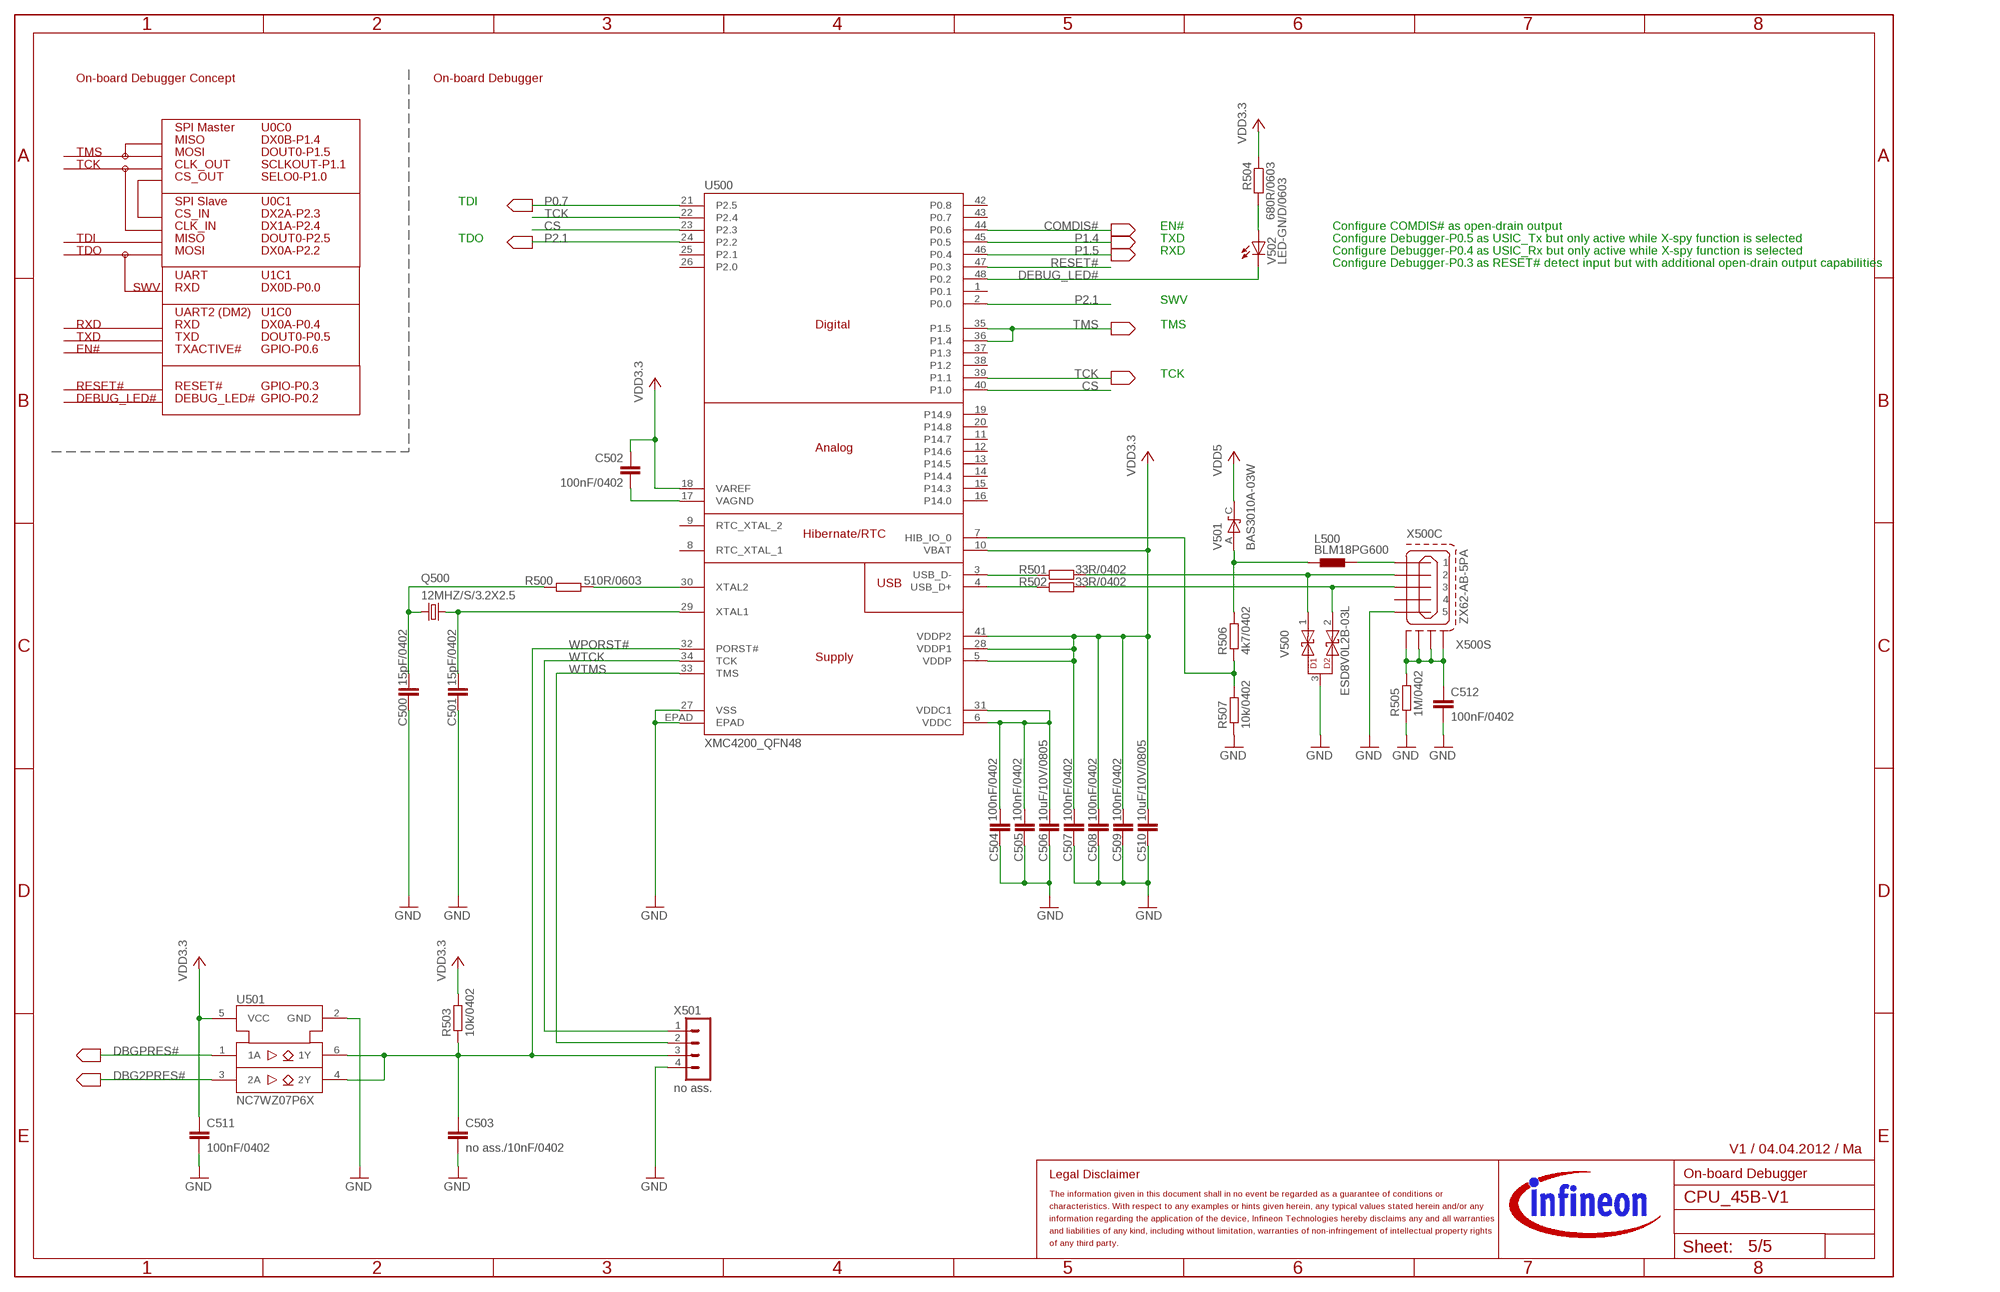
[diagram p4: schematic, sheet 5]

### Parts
C500  15pF/0402  C-EUC0402  [C0402]
C501  15pF/0402  C-EUC0402  [C0402]
C502  100nF/0402  C-EUC0402  [C0402]
C503  no ass./10nF/0402  C-EUC0402  [C0402]
C504  100nF/0402  C-EUC0402  [C0402]
C505  100nF/0402  C-EUC0402  [C0402]
C506  10uF/10V/0805  C-EUC0805K  [C0805K]
C507  100nF/0402  C-EUC0402  [C0402]
C508  100nF/0402  C-EUC0402  [C0402]
C509  100nF/0402  C-EUC0402  [C0402]
C510  10uF/10V/0805  C-EUC0805K  [C0805K]
C511  100nF/0402  C-EUC0402  [C0402]
C512  100nF/0402  C-EUC06030402  [C0402]
L500  BLM18PG600  L_EU_L0603  [L1608]
Q500  12MHZ/S/3.2X2.5  NX3225_22PAD  [32X25_2PAD]
R500  510R/0603  R-EU_R0603  [R0603]
R501  33R/0402  R-EU_R0402  [R0402]
R502  33R/0402  R-EU_R0402  [R0402]
R503  10k/0402  R-EU_R0402  [R0402]
R504  680R/0603  R-EU_R0603  [R0603]
R505  1M/0402  R-EU_R06030402  [R0402]
R506  4k7/0402  R-EU_R0402  [R0402]
R507  10k/0402  R-EU_R0402  [R0402]
U500  XMC4200_QFN48  [QFN-48-7X7]
U501  NC7WZ07P6X  NC7WZ07_2P6X  [SC70-6L]
V500  ESD8V0L2B-03L  [TSLP-3-1]
V501  BAS3010A-03W  BAT60  [SOD323-R]
V502  LED-GN/D/0603  LEDCHIPLED_0603  [CHIPLED_0603]
X500  ZX62-AB-5PA  ZX62-AB-5PA_MICRO-USB  [ZX62-AB-5PA_MICRO-USB]
X501  no ass.  MA04-1  [MA04-1]

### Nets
COMDIS#: U500.44(P0.6) ; also sheet 3,4
CS: U500.23(P2.3) U500.40(P1.0)
DBG2PRES#: U501.3(2A) ; also sheet 4
DBGPRES#: U501.1(1A) ; also sheet 3,4
DEBUG_LED#: U500.48(P0.2) V502.C
GND: C500.2 C501.2 C503.2 C504.2 C505.2 C506.2 C507.2 C508.2 C509.2 C510.2 C511.2 C512.2 R505.1 R507.1 U500.27(VSS) U500.EPAD U501.2(GND) V500.3 X500.5 X501.4 ; also sheet 2,3,4
N$29: L500.2 X500.1
N$30: C512.1 R505.2 X500.S1(S:S1) X500.S2(S:S2) X500.S3(S:S3) X500.S4(S:S4)
N$34: R506.1 R507.2 U500.7(HIB_IO_0)
N$37: R501.2 V500.1 X500.2
N$41: R502.2 V500.2 X500.3
N$44: C500.1 Q500.2 R500.2
N$45: C501.1 Q500.1 U500.29(XTAL1)
N$46: R500.1 U500.30(XTAL2)
N$47: L500.1 R506.2 V501.A
N$50: C502.2 U500.17(VAGND)
N$51: R504.2 V502.A
P0.7: U500.21(P2.5) ; also sheet 2,3,4
P1.4: U500.45(P0.5) ; also sheet 3,4
P1.5: U500.46(P0.4) ; also sheet 3,4
P2.1: U500.2(P0.0) U500.24(P2.2) ; also sheet 3,4
RESET#: U500.47(P0.3) ; also sheet 2,3,4
TCK: U500.22(P2.4) U500.39(P1.1) ; also sheet 3,4
TMS: U500.35(P1.5) U500.36(P1.4) ; also sheet 3,4
VDD3.3: C502.1 C507.1 C508.1 C509.1 C510.1 C511.1 R503.2 R504.1 U500.5(VDDP) U500.10(VBAT) U500.18(VAREF) U500.28(VDDP1) U500.41(VDDP2) U501.5(VCC) ; also sheet 2,3,4
VDD5: V501.C ; also sheet 2,4
WPORST#: C503.1 R503.1 U500.32(PORST#) U501.4(2Y) U501.6(1Y) X501.3
WTCK: U500.34(TCK) X501.1
WTMS: U500.33(TMS) X501.2
WUSB_DM: R501.1 U500.3(USB_D-)
WUSB_DP: R502.1 U500.4(USB_D+)
WVDDC: C504.1 C505.1 C506.1 U500.6(VDDC) U500.31(VDDC1)
Unconnected: U500.1(P0.1) U500.8(RTC_XTAL_1) U500.9(RTC_XTAL_2) U500.11(P14.7) U500.12(P14.6) U500.13(P14.5) U500.14(P14.4) U500.15(P14.3) U500.16(P14.0) U500.19(P14.9) U500.20(P14.8) U500.25(P2.1) U500.26(P2.0) U500.37(P1.3) U500.38(P1.2) U500.42(P0.8) U500.43(P0.7) X500.4

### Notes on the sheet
- On-board Debugger Concept | On-board Debugger
- SPI Master | U0C0
- MISO | DX0B-P1.4
- TMS | MOSI | DOUT0-P1.5
- TCK | CLK_OUT | SCLKOUT-P1.1
- CS_OUT | SELO0-P1.0
- SPI Slave | U0C1 | TDI
- CS_IN | DX2A-P2.3
- CLK_IN | DX1A-P2.4 | EN# | Configure COMDIS# as open-drain output
- TDI | MISO | DOUT0-P2.5 | TDO | TXD | Configure Debugger-P0.5 as USIC_Tx but only active while X-spy function is selected
- TDO | MOSI | DX0A-P2.2 | RXD | Configure Debugger-P0.4 as USIC_Rx but only active while X-spy function is selected
- Configure Debugger-P0.3 as RESET# detect input but with additional open-drain output capabilities
- UART | U1C1
- SWV | RXD | DX0D-P0.0
- SWV
- UART2 (DM2) | U1C0
- RXD | RXD | DX0A-P0.4 | TMS
- TXD | TXD | DOUT0-P0.5
- EN# | TXACTIVE# | GPIO-P0.6
- TCK
- RESET# | RESET# | GPIO-P0.3
- DEBUG_LED# | DEBUG_LED# | GPIO-P0.2
- V1 / 04.04.2012 / Ma
- On-board Debugger

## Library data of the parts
ADJ_1-ADJ_3 = Global:FIDUCIAL: Fiducial
C200 C202 C204 C205 C208 C210 C211 C300-C302 C305-C307 C309-C312 C315-C319 C321 C322 C406 C413 C415-C417 C430-C436 C512 = DsC:C-EUC0603
C212 C308 C323-C325 C405 C407 = rcl:C-EU: CAPACITOR, European symbol
C213 C414 = rcl:CPOL-EU: POLARIZED CAPACITOR, European symbol
C400 C401 C500-C505 C507-C509 C511 = DsC:C-EUC0402
C506 C510 = HMI_OLED-V1:C-EU: CAPACITOR, European symbol
JP300 = XTV254:POWERSCALE
L201 L300 L301 L500 = PDFerr:L_EU_
Q301 = mars:FC135-32.768KHZ
Q302 Q500 = Quarz:NX3225_2
Q404 = DsTran:BC858C
R200 R202-R207 R301-R307 R309 R310 R313 R400 R401 R405-R408 R413-R417 R419 R420 R422 R429-R432 R500 R504 R505 = DsR:R-EU_R0603
R300 = RPot:POTI/10K/VERT: ALPS RK09K/RK09D Series > RK09K1130A8G
R402-R404 R410 R421 R423-R427 R501-R503 R506 R507 = DsR:R-EU_R0402
SJ1-SJ5 = Rs_RND:SJ0402
SW300 = MSwitch:219-02*: Surface Mount DIP Switch Series 219 SMT CTS Electronic Components Sourc: www.ctscorp.com
SW400-SW402 = MSwitch:FSM2JSMA
TP404-TP407 = pinhead:PINHD-1X1: PIN HEADER
U200 = IvregL:STMPS2151
U300 = XMC4000_v4.16:XMC4500_LFBGA144: Infineon XMC4500 144Pin LFBGA ARM Cortex M4
U301 U303 U304 U306 = IASwit:74LVC1G66+PWR
U302 = IMFRom:W25Q80BV
U401 = IvregL:IFX1763_PAD: Infineon IFX1763 LDO with exposed pad Device: - IFX1763_PADNOP = device without solder paste on the exposed pad - IFX1763_PADWIP = device with solder paste on the exposed pad
U430 = IMSD33:MT48LC4M16A2B4-7E
U500 = XMC4000_v4.16:XMC4200_QFN48
U501 = ItGate:NC7WZ07_2
V200 V408 V501 = DsDiod:BAT60
V201 V500 = DsDiod:ESD8V0L2B-03L
V300 V301 V401-V403 V407 V502 = led:LED: LED
V404 V405 = DsDiod:BAT54-02V
V406 = DsDiod:BAV70
X200-X202 = XSE080:HSEC8_MATING-CARD
X203 X500 = XSRRND:ZX62-AB-5PA_MICRO-USB
X400 = Xsv127:FTSH-110-01-L-DV-K-P
X401 = Xsv127:XE3K_DM2+CTX
X402 = XRnd:BK-885
X501 = XTV254:MA04-1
